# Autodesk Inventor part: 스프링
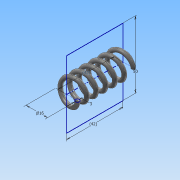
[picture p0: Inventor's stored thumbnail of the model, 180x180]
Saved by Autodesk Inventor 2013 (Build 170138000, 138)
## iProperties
Created: 2015-12
Part Number: 스프링
Material: 강철, 탄소
Document SubType Name: Modeling
Designer: Administrator
Density: 7.87 g/cm^3
Mass: 16.5097 g
Surface Area: 28.4714 cm^2
Volume: 2.0978 cm^3
Author: Administrator
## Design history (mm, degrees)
sketch "스케치2"
  geometry: L1 (0, 0)-(0, 42); L2 (0, 0)-(8, 0); L3 (0, 42)-(8, 42); C1 r 1.5 at (8, 0)
  constraints: 6 end point, 1 centre point, 1 horizontal alignment, 1 parallel, 1 perpendicular, 1 vertical
  dimensions: "d0" = 42 distance of L1.start L1.end (derived); "d1" = 3 diameter of C1; "d2" = 16 diameter of L2.end L1
feature "코일1" sketch "스케치2" pitch "d3" = 10; turns "d5" = 6; dims "d4" = 41.99997 (computed from d0), "d6" = 0, angle "d7" = 90 deg, angle "d8" = 90 deg, "d9" = 0, "d10" = 0
sketch "스케치3"
  geometry: L1 (42, 25)-(0, 25); L2 (0, 25)-(0, -25); L3 (0, -25)-(42, -25); L4 (42, -25)-(42, 25); 2 further points
  constraints: 8 end point, 2 parallel, 1 coincident, 1 horizontal, 1 midpoint, 1 perpendicular
  dimensions: "d11" = 41.99997 distance of L2.end L3.end (derived); "d13" = 50 distance of L3.end L1.start
extrude "돌출1" sketch "스케치3" stored distance "d14" = 10; taper "d15" = 0 deg
node "솔리드1"
